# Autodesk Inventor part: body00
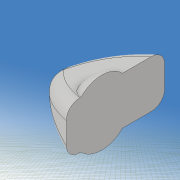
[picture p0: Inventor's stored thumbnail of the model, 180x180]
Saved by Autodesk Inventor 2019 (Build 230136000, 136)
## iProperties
Created: 2020-12
Part Number: body00
Material: 一般
Document SubType Name: Modeling
Designer: kikut
Density: 1 g/cm^3
Appearance: 既定
Mass: 87.6477 g
Surface Area: 156.124 cm^2
Volume: 87.6477 cm^3
Author: kikut
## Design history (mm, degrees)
sketch "スケッチ1"
  geometry: L1 (-100, -20)-(100, -20); L2 (100, -20)-(100, 20); L3 (100, 20)-(-100, 20); L4 (-100, 20)-(-100, -20); L5 (-100, -20)-(100, 20); L6 (100, -20)-(-100, 20); 1 further point
  constraints: 12 end point, 2 midpoint, 2 parallel, 1 horizontal, 1 perpendicular
  dimensions: "d0" = 40 distance of L3.end L1.start; "d1" = 200 distance of L2.end L3.end
extrude "押し出し1" new body sketch "スケッチ1" stored distance "d2" = 60; taper "d3" = 0 deg
sketch "スケッチ2"
  geometry: L1 (0, -60)-(0, 0) reference; L2 (200, -60)-(200, 0) reference; L3 (0, 0)-(200, 0) reference; L4 (200, -60)-(0, -60) reference; L5 (0, -26)-(0, -32); L6 (194, -10)-(194, -13); L7 (194, -13)-(174, -33); L8 (174, -33)-(200, -58); L9 (-20, 20)-(220, 20); L10 (220, 20)-(220, -100); L11 (220, -100)-(-20, -100); L12 (-20, -100)-(-20, 20); 12 further points
  constraints: 16 end point, 4 point on line, 2 parallel, 2 vertical, 1 horizontal, 1 perpendicular, 14 other
  dimensions: "d4" = 32 distance from line of point (32, -12) L1; "d5" = 50 horizontal distance of point (32, -12) point (82, -11); "d6" = 50 horizontal distance of point (132, -17) point (82, -11); "d7" = 12 distance from line of point (32, -12) L3; "d8" = 11 distance from line of point (82, -11) L3; "d10" = 17 distance from line of point (132, -17) L3; "d11" = 26 distance from line of L5.start L3; "d12" = 0 distance from line of point (200, -60) L4; "d13" = 28 distance from line of L5.end L4; "d14" = 12 distance from line of point (28, -48) L4; "d15" = 10 distance from line of point (80, -50) L4; "d16" = 16 distance from line of point (130, -44) L4; "d17" = 28 distance from line of point (28, -48) L1; "d19" = 50 horizontal distance of point (130, -44) point (80, -50); "d20" = 80 distance from line of point (80, -50) L1; "d21" = 6 distance from line of L6.start L2; "d22" = 36 distance from line of point (164, -24) L2; "d23" = 24 distance from line of point (176, -20) L2; "d24" = 10 distance from line of L6.start L3; "d25" = 20 distance from line of point (176, -20) L3; "d26" = 24 distance from line of point (164, -24) L3; "d27" = 40 distance from line of point (160, -40) L2; "d28" = 25 distance from line of point (175, -47.5) L2; "d29" = 12.5 distance from line of point (175, -47.5) L4; "d30" = 20 distance from line of L4 point (160, -40); "d31" = 3 distance of L6.start L6.end; "d32" = 33 distance from line of L7.end L3; "d33" = 26 distance from line of L7.end L2; "d34" = 2 distance of L8.end L2.start; "d35" = 120 distance of L11.end L9.start; "d36" = 240 distance of L10.end L11.end; "d37" = 20 distance between parallel lines of L1 L12; "d38" = 20 distance between parallel lines of L3 L9
extrude "押し出し2" cut sketch "スケッチ2" extent not by distance; stored distance "d39" = 0.02; taper "d40" = 0 deg
sketch "スケッチ8"
  geometry: L1 (-100, -20)-(-100, 20) reference; L2 (100, 20)-(100, -20) reference; L3 (-142.805, 0)-(142.831, 0) reference; L4 (110, 30)-(-110, 30); L5 (-110, 30)-(-110, -30); L6 (-110, -30)-(110, -30); L7 (110, -30)-(110, 30); L8 (110, 30)-(-110, -30); L9 (-110, 30)-(110, -30); L10 (-100, -2)-(-100, 2); L11 (100, -3)-(100, 3); 7 further points
  constraints: 16 end point, 4 point on line, 2 midpoint, 2 parallel, 2 perpendicular, 1 collinear, 1 horizontal, 10 other
  dimensions: "d93" = 2 vertical distance of point (0, 0) L10.end; "d94" = 2 vertical distance of L10.start point (0, 0); "d95" = 35 distance from line of point (-65, -10) L1; "d96" = 0 horizontal distance of point (-65, 10) point (-65, -10); "d97" = 10 vertical distance of point (0, 0) point (-65, -10); "d98" = 10 vertical distance of point (-65, 10) point (0, 0); "d99" = 100 distance from line of point (0, -10) L1; "d100" = 0 horizontal distance of point (0, 10) point (0, -10); "d101" = 10 distance of point (0, -10) point (0, 0); "d102" = 10 distance of point (0, 0) point (0, 10); "d103" = 160 distance from line of point (60, -4) L1; "d104" = 0 horizontal distance of point (60, 4) point (60, -4); "d105" = 4 distance from line of L3 point (60, -4); "d106" = 4 distance from line of L3 point (60, 4); "d107" = 3 distance from line of L11.start L3; "d108" = 3 distance from line of L11.end L3; "d109" = 220 distance of L5.end L6.end; "d110" = 60 distance of L4.end L5.end
extrude "押し出し6" cut sketch "スケッチ8" extent not by distance; stored distance "d111" = 10; taper "d112" = 0 deg
sketch "スケッチ9" dims "d113" = 20, "d114" = 12
  geometry: L1 (-29, -18)-(21, -18); L2 (21, -18)-(21, 22); L3 (21, 22)-(-29, 22); L4 (-29, 22)-(-29, -18); L5 (-29, -18)-(21, 22); L6 (21, -18)-(-29, 22); 2 further points; 1 other entity
  constraints: 12 end point, 2 midpoint, 2 parallel, 1 coincident, 1 horizontal, 1 perpendicular, 2 other
  dimensions: "d115" = 50 distance of L2.end L3.end; "d116" = 40 distance of L1.end L2.end
extrude "押し出し7" cut sketch "スケッチ9" distance "d117" = 150; taper "d118" = 0 deg
fillet "フィレット4" dims "d119" = 4
fillet "フィレット5" dims "d120" = 4
fillet "フィレット6" dims "d121" = 2
node "作業平面2"
sketch "スケッチ10"
  geometry: L1 (0, -41.439)-(0, 38.458) reference; L2 (141.833, 0)-(-140.631, 0) reference; L3 (82.55, 12.983)-(81.45, -4.983); A1 r 9 centre (82, 4) between (82.55, 12.983) and (81.45, -4.983); 1 further point
  constraints: 2 end point, 2 point on circle, 1 centre point
  dimensions: "d123" = 82 distance from line of L1 A1.centre; "d124" = 4 distance from line of L2 A1.centre; "d125" = 9 radius of A1; "d126" = 180 deg dimension on A1.centre L3.end L3.start; "d127" = 90 deg dimension on L3.end point (0, 0) A1.centre
revolve "回転1" sketch "スケッチ10" stored, may be unused: angle "d128" = 90 deg
mirror "ミラー1"
sketch "スケッチ11"
  geometry: L1 (100, 30)-(85, 30); L2 (85, 30)-(85, -30); L3 (85, -30)-(100, -30); L4 (100, -30)-(100, 30); L5 (0, -40.648)-(0, 34.486) reference; L6 (140.69, 0)-(-139.196, 0) reference; L7 (120, 53.792)-(-120, 53.792); L8 (-120, 53.792)-(-120, -46.208); L9 (-120, -46.208)-(120, -46.208); L10 (120, -46.208)-(120, 53.792); 1 further point
  constraints: 16 end point, 4 parallel, 2 horizontal, 2 perpendicular, 2 other
  dimensions: "d129" = 85 distance between parallel lines of L5 L2; "d130" = 15 distance of L1.start L1.end; "d131" = 60 distance of L3.end L1.start; "d132" = 100 distance of L9.end L7.start; "d133" = 240 distance of L7.start L7.end
extrude "押し出し8" cut sketch "スケッチ11" stored distance "d134" = 40; taper "d135" = 0 deg
node "ソリッド1"
other parameters: "d122" = -1
